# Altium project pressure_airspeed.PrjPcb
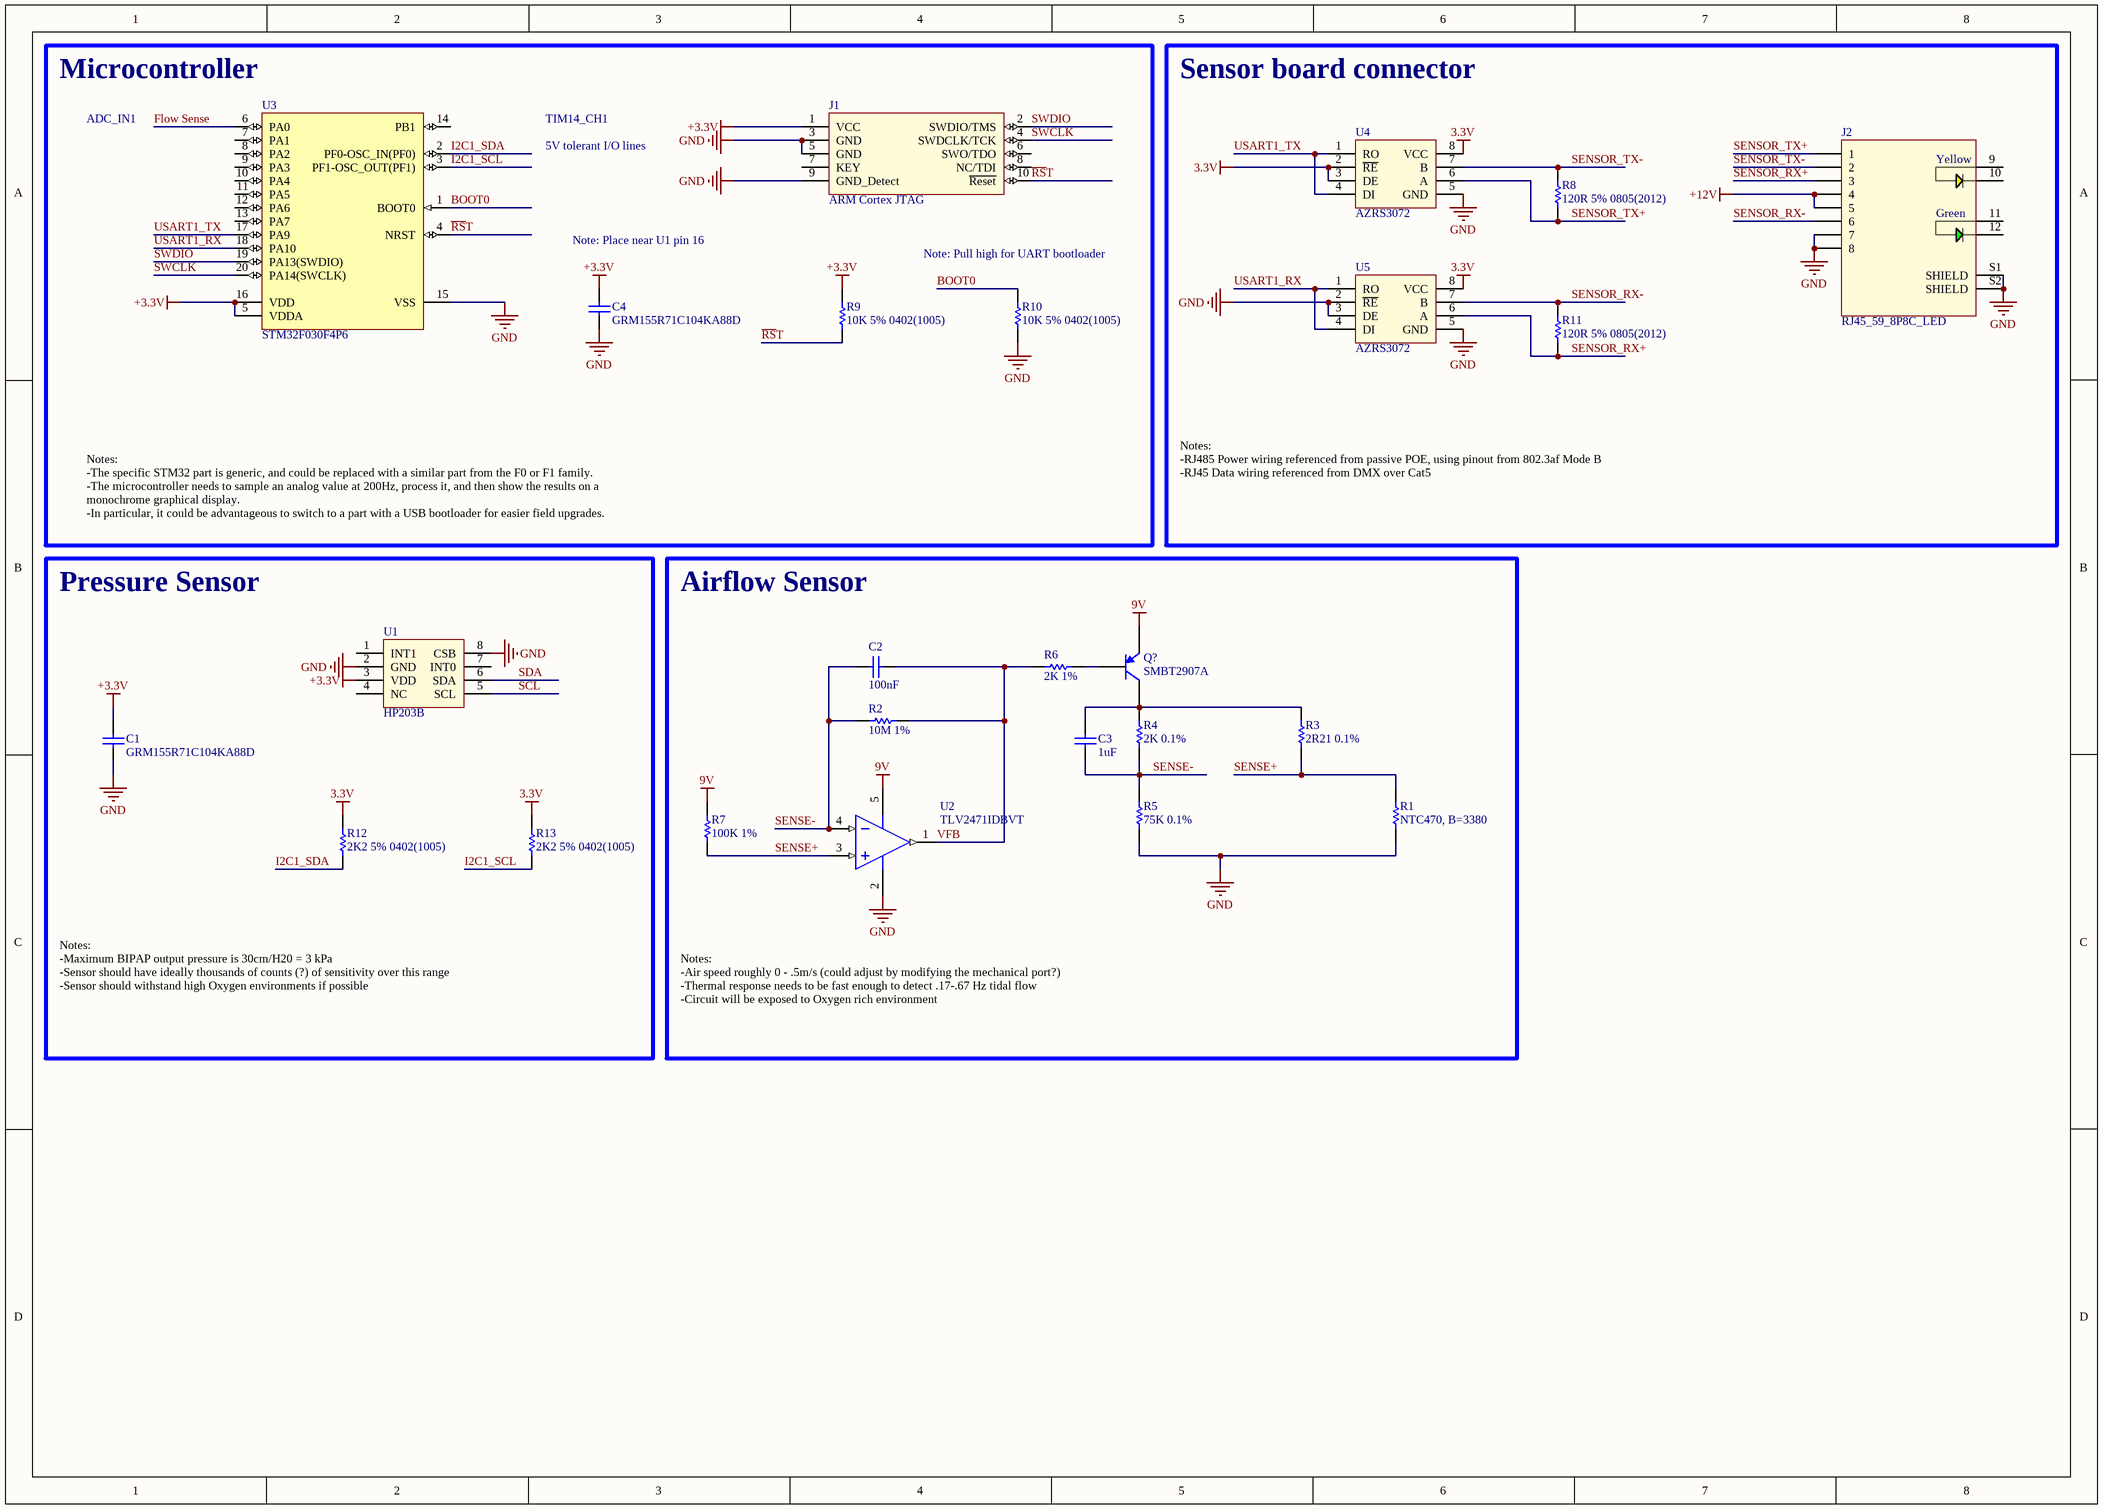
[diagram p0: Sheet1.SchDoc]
1 sheet, 25 parts. Net scope: global (net labels, ports and power ports of the same name join across sheets).
Board file: PCB1.PcbDoc

## Sheet Sheet1.SchDoc
size A3; DocumentNumber: 1; SheetNumber: 1; SheetTotal: 1

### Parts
C1  GRM155R71C104KA88D  [CAPC1005X55X25ML05T10]
C2  100nF  [CAPC1005X55X25ML05T10]
C3  1uF  [CAPC1005X55X25ML05T10]
C4  GRM155R71C104KA88D  [CAPC1005X55X25ML05T10]
J1  ARM Cortex JTAG  [1.27mm 2x5 SMD Header - no paste]
J2  RJ45_59_8P8C_LED  [RJ45_59_8P8C_LED]
Q?  SMBT2907A  [INF-SOT23_N]
R1  NTC470, B=3380  [RESC1005X40X25NL05T05]
R2  10M 1%  [RESC1005X40X25ML05T10]
R3  2R21 0.1%  [RESC1005X40X25ML05T10]
R4  2K 0.1%  [RESC1005X40X25ML05T10]
R5  75K 0.1%  [RESC1005X40X25ML05T10]
R6  2K 1%  [RESC1005X40X25NL05T05]
R7  100K 1%  [RESC1005X40X25ML05T10]
R8  120R 5% 0805(2012)  [RESC0805(2012)_N]
R9  10K 5% 0402(1005)  [RESC0402(1005)_N]
R10  10K 5% 0402(1005)  [RESC0402(1005)_N]
R11  120R 5% 0805(2012)  [RESC0805(2012)_N]
R12  2K2 5% 0402(1005)  [RESC0402(1005)_N]
R13  2K2 5% 0402(1005)  [RESC0402(1005)_N]
U1  HP203B  [HP203B]
U2  TLV2471IDBVT  [DBV0005A_L]
U3  STM32F030F4P6  [STM-TSSOP20_L]
U4  AZRS3072  [SOIC127P600X175-8N]
U5  AZRS3072  [SOIC127P600X175-8N]

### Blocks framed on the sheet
Microcontroller: C4 J1 R9 R10 U3
Sensor board connector: J2 R8 R11 U4 U5
Pressure Sensor: C1 R12 R13 U1
Airflow Sensor: C2 C3 Q? R1-R7 U2

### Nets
3.3V: R12.2 R13.2 U4.2(~{RE}) U4.3(DE) U4.8(VCC) U5.8(VCC)
9V: Q?.2(E) R7.1 U2.5(VDD)
+3.3V: C1.2 C4.2 J1.1(VCC) R9.1 U1.3(VDD) U3.5(VDDA) U3.16(VDD)
+12V: J2.4 J2.5
GND: C1.1 C4.1 J1.3(GND) J1.5(GND) J1.9(GND_Detect) J2.7 J2.8 J2.S1(SHIELD) J2.S2(SHIELD) R1.1 R5.1 R10.2 U1.2(GND) U1.8(CSB) U2.2(GND) U3.15(VSS) U4.5(GND) U5.2(~{RE}) U5.3(DE) U5.5(GND)
~{RS}T: J1.10(~{Reset}) R9.2 U3.4(NRST)
BOOT0: R10.1 U3.1(BOOT0)
Flow Sense: U3.6(PA0)
I2C1_SCL: R13.1 U3.3(PF1-OSC_OUT(PF1))
I2C1_SDA: R12.1 U3.2(PF0-OSC_IN(PF0))
SCL: U1.5(SCL)
SDA: U1.6(SDA)
SENSE+: R1.2 R3.1 R7.2 U2.3(IN+)
SENSE-: C2.2 C3.2 R2.2 R4.1 R5.2 U2.4(IN-)
SENSOR_RX+: J2.3 R11.1 U5.6(A)
SENSOR_RX-: J2.6 R11.2 U5.7(B)
SENSOR_TX+: J2.1 R8.1 U4.6(A)
SENSOR_TX-: J2.2 R8.2 U4.7(B)
SWCLK: J1.4(SWDCLK/TCK) U3.20(PA14(SWCLK))
SWDIO: J1.2(SWDIO/TMS) U3.19(PA13(SWDIO))
USART1_RX: U3.18(PA10) U5.1(RO) U5.4(DI)
USART1_TX: U3.17(PA9) U4.1(RO) U4.4(DI)
VFB: C2.1 R2.1 R6.2 U2.1(OUT)
NetC3_1: C3.1 Q?.3(C) R3.2 R4.2
NetQ?_1: Q?.1(B) R6.1

Not connected (* = marked no-connect by the designer): J1 6(SWO/TDO) 7(KEY) 8(NC/TDI); J2 9(Yellow_Anode) 10(Yellow_Cathode) 11(Green_Anode) 12(Green_Cathode); U1 1(INT1) 4(NC) 7(INT0); U3 7(PA1) 8(PA2) 9(PA3) 10(PA4) 11(PA5) 12(PA6) 13(PA7) 14(PB1)

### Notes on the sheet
- ADC_IN1
- TIM14_CH1
- 5V tolerant I/O lines
- Note: Place near U1 pin 16
- (near R10) Note: Pull high for UART bootloader
- Notes:
  -RJ485 Power wiring referenced from passive POE, using pinout from 802.3af Mode B
  -RJ45 Data wiring referenced from DMX over Cat5
- Notes:
  -The specific STM32 part is generic, and could be replaced with a similar part from the F0 or F1 family.
  -The microcontroller needs to sample an analog value at 200Hz, process it, and then show the results on a monochrome graphical display.
  -In particular, it could be advantageous to switch to a part with a USB bootloader for easier field upgrades.
- Notes:
  -Maximum BIPAP output pressure is 30cm/H20 = 3 kPa
  -Sensor should have ideally thousands of counts (?) of sensitivity over this range
  -Sensor should withstand high Oxygen environments if possible
- Notes:
  -Air speed roughly 0 - .5m/s (could adjust by modifying the mechanical port?)
  -Thermal response needs to be fast enough to detect .17-.67 Hz tidal flow
  -Circuit will be exposed to Oxygen rich environment

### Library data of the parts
C1 C3 C4 = CMP-2100-03641-1: Chip Capacitor, 0.1 uF, +/- 10%, 16 V, -55 to 125 degC, 0402 (1005 Metric), RoHS, Tape and Reel; Manufacturer: Murata; Material: Ceramic; Insulation Resistance: 10GR; Voltage: 16V; Dielectric: X7R; Capacitance: 100nF
C2 = CMP-2100-03641-1: Chip Capacitor, 0.1 uF, +/- 10%, 16 V, -55 to 125 degC, 0402 (1005 Metric), RoHS, Tape and Reel; Manufacturer: Murata; Material: Ceramic; Insulation Resistance: 10GR; Voltage: 16V; Dielectric: X7R
J1 = ARM Cortex JTAG: Arm Cortex 10-pin JTAG connector; Manufacturer: Unknown/Generic
J2 = RJ45_59_8P8C_LED: Generic RJ49 jack with LED and without magnetics; Manufacturer: Unknown/Generic
Q? = CMP-1178-00003-1: PNP Silicon Switching Transistor, 60 V VCEO, 600 mA IC, SOT23, Reel, Green; Manufacturer: Infineon; VCBO (max): 60 V; VCE: 10 V; IC: 150 mA; IC (max): 600 mA; Green: TRUE; VEBO (max): 5 V; ICBO (max): 10 nA
R1 R6 = CMP-2002-01187-1: Manufacturer: Panasonic; Part Number: ERT-J0EV474J
R2-R5 R7 = CMP-2002-07472-1: Part Number: RC0402FR-071KL; Manufacturer: Yageo / Phycomp
R8 R11 = CMP-1013-00052-1: 120R 0.125W 5% 0805 (2012 Metric)  SMD; Case-Metric: 2012; Value: 120.00 Ohm; Case-EIA: 0805
R9 R10 = CMP-1011-00098-1: 10K 0.063W 5% 0402 (1005 Metric)  SMD; Case-Metric: 1005; Value: 10000.00 Ohm; Case-EIA: 0402
R12 R13 = CMP-1011-00082-1: 2K2 0.063W 5% 0402 (1005 Metric)  SMD; Value: 2200.00 Ohm; Case-EIA: 0402; Case-Metric: 1005
U1 = HP203B: PRECISION BAROMETER AND ALTIMETER SENSOR; Manufacturer: HopeRF
U2 = CMP-0271-00230-3: Single Low-Power Rail-to-Rail Input / Output Operational Amplifier, 2.7 to 6 V, -40 to 125 degC, 5-pin SOT23 (DBV5), Green (RoHS & no Sb/Br); Manufacturer: Texas Instruments; Number of Channels: 1; Vio (25C)(Max)(mV): 2.2; Total Supply Voltage(Max)(+5V is 5, +/-5V is 10): 6; CMRR(Min)(dB): 61; Total Supply Voltage(Min)(+5V is 5, +/-5V is 10): 2.7; Iq per channel(Max)(mA): 0.75; Sub Family: Low Supply Voltage Amplifier (<=2.7V), Precision Amplifier; Offset Drift(Typ)(uV/C): 0.4; Slew Rate(Typ)(V/us): 1.4; IIB(Max)(pA): 50; Vn at 1kHz(Typ)(nV/rtHz): 15
U3 = CMP-0304-00039-2: ARM Cortex-M0 32-bit MCU, 16 KB Flash, 4 KB Internal RAM, 15 I/Os, 20-pin TSSOP, -40 to 85 degC, Tube; I/Os (High Current): 15; FLASH Size (Prog) (kB): 16; Internal RAM Size (kB): 4; Supply Voltage(Vcc) min (V): 2.4; Operating Frequency(F) (Processor speed) (MHz): 48
U4 U5 = AZRS3072: ESD-Protected, Slew-Rate-Limited, True Fail-Safe 3.3V RS485 Transceiver IC; Manufacturer: Amazing Microelectronic Corp.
